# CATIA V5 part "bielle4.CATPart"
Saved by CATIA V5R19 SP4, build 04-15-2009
Part number: bielle4
Bounding box of the stored display mesh (mm): x -7 to 7, y -5.85 to 69.85, z 0 to 12
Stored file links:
  E:\IAO_2010\iao\IAO_MMS_Groupe1\Problemes\tlampure\tlampure\tlampure\bielle4.CATPart
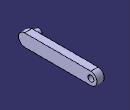
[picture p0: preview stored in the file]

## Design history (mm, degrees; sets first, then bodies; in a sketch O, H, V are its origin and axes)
Parameters
  Lb4 = 64 mm
Body1 (main body)
  Sketch1 on yz-plane, origin (0, 0, 0), H (0, 1, 0), V (0, 0, 1)
    line L1 (0, 0) -> (64, 0)
    arc A1 centre (64, 6) radius 6 from (64, 0) to (64, 12) ccw
    line L2 (64, 12) -> (0, 12)
    point P4 (0, 12)
    arc A2 centre (0, 6) radius 6 from (0, 12) to (0, 0) ccw
    length L2 = 64 {= Lb4}
    distance L2 L1 = 12
    horizontal: L1 H
    tangency: A1 L1, L2 A1, A2 L1, A2 L2
    coincidence: P4 V
  Pad1: profile Sketch1, direction (1, 0, 0), length 7
  Sketch2 on end face of Pad1, origin (7, 0, 0), H (0, 1, 0), V (0, 0, 1)
    circle A1 centre (64, 6) radius 3
    point P1 (64, 6)
    reference projected line E1 (0, 0) -> (60, 0) from edge [face of Pad1 from Sketch1.L1 | end face of Pad1]
    distance P1 E1 = 6
    distance V P1 = 64 {= Lb4}
  Pocket1: profile Sketch2, direction (-1, 0, 0), length 7
  Sketch3 on yz-plane, origin (0, 0, 0), H (0, 1, 0), V (0, 0, 1)
    circle A1 centre (0, 6) radius 3
    point P1 (0, 6)
    reference projected line E1 (0, 0) -> (60, 0) from edge [face of Pad1 from Sketch1.L1 | end face of Pad1]
    distance E1 P1 = 6
    coincidence: P1 V
  Pad2: profile Sketch3, direction (-1, 0, 0), length 7
  Sketch4 on end face of Pad1, origin (7, 0, 0), H (0, 1, 0), V (0, 0, 1)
